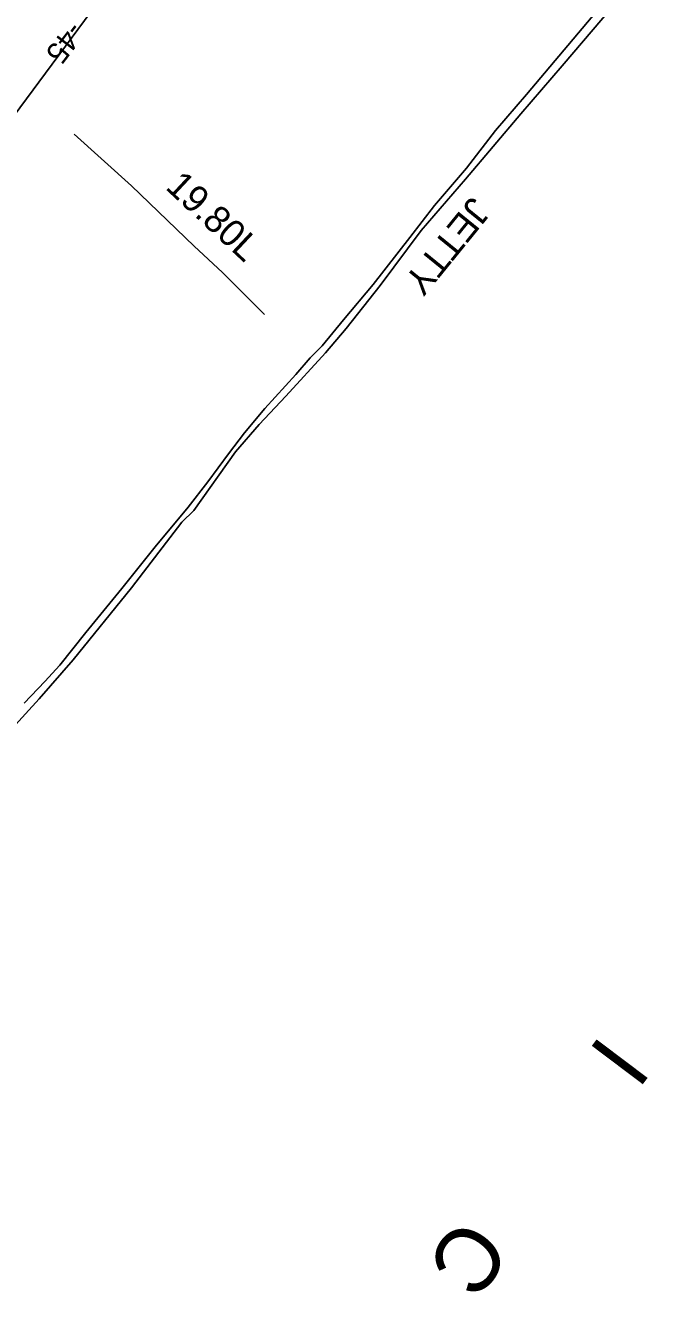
# Model space of a CAD drawing. Extents: x 3879599 to 3900814, y 146526 to 168888.
# Drawn here: x 3891224 to 3892197, y 152191 to 154174 of the extents above; entities that cross this region are included whole.
import ezdxf

# ---------------------------------------------------------------- set-up
doc = ezdxf.new("R2010")
doc.units = 0
for name, color, linetype in [('V-LEVE-TOET', 7, 'Continuous'), ('V-RIVR-IDEN', 7, 'Continuous'), ('V-RIVR-JETY', 7, 'Continuous'), ('V-RIVR-RANG', 7, 'Continuous'), ('V-STRM-FMON', 7, 'Continuous'), ('V-TOPO-DPTH', 7, 'Continuous')]:
    doc.layers.add(name, color=color, linetype=linetype)

msp = doc.modelspace()

# ---------------------------------------------------------------- linework, layer by layer
at = {"layer": 'V-LEVE-TOET'}
msp.add_lwpolyline([(3891598, 153721.7), (3891532.2, 153787.4), (3891488, 153828.6), (3891389.7, 153922.8), (3891300.1, 154003.5)], dxfattribs=at)
at = {"layer": 'V-RIVR-JETY'}
for points in [[(3891478.4, 153419.9), (3891509.4, 153459.7), (3891541.4, 153503.7), (3891566.8, 153536.3), (3891598.5, 153574.2), (3891647.1, 153627.9), (3891669.2, 153653.6), (3891688.3, 153672.4), (3891721.5, 153713), (3891768.2, 153768.5), (3891825.3, 153842), (3891863.7, 153892.2), (3891913.8, 153950.4), (3891959.3, 154009.7), (3892007.9, 154065.7), (3892081.1, 154152.3), (3892145.8, 154229.3)], [(3892142.7, 154203.1), (3892063.5, 154110.7), (3891999.2, 154035.6), (3891912.5, 153933.3), (3891843, 153852.9), (3891779.2, 153766.8), (3891725.5, 153699.4), (3891693.4, 153661.8), (3891631.6, 153594), (3891589.7, 153549.5), (3891552.7, 153506.5), (3891487.2, 153415.1), (3891468.8, 153396.7)], [(3891222.1, 153113.5), (3891254.3, 153147.2), (3891277.9, 153172.9), (3891318.6, 153224.2), (3891375, 153292.8), (3891429.1, 153360.6), (3891463.4, 153401.9), (3891478.4, 153419.9)], [(3891468.8, 153396.7), (3891390.1, 153293.7), (3891298.6, 153181.1), (3891245.6, 153120.2), (3891197.3, 153067.3), (3891166.7, 153029.4), (3891146.1, 153004.8), (3891120.7, 152977.2), (3891084.9, 152927.5), (3891035.4, 152854.5), (3890985.4, 152790.9), (3890941, 152738), (3890883.7, 152678.2), (3890811.7, 152615.5), (3890745, 152553.6), (3890711.6, 152527.1), (3890646.5, 152483.4), (3890615.7, 152466.3), (3890539.2, 152428.2), (3890514.7, 152415)]]:
    msp.add_lwpolyline(points, dxfattribs=at)
at = {"layer": 'V-TOPO-DPTH'}
msp.add_lwpolyline([(3891753.9, 154772.9), (3891153.5, 153962.5)], dxfattribs=at)

# ---------------------------------------------------------------- texts
at = {"layer": 'V-RIVR-IDEN'}
for s, p in [('I', (3892125, 152597.1)), ('C', (3891906.7, 152313.3))]:
    msp.add_text(s, height=100, rotation=232.9925, dxfattribs=at).set_placement(p)
at = {"layer": 'V-RIVR-JETY'}
msp.add_text('JETTY', height=42, rotation=230.9182, dxfattribs=at).set_placement((3891922.2, 153907.9))
at = {"layer": 'V-RIVR-RANG'}
msp.add_text('-45', height=33.5, rotation=232.6215, dxfattribs=at).set_placement((3891293.2, 154182.3))
at = {"layer": 'V-STRM-FMON'}
msp.add_text('19.80L', height=42, rotation=316.914, dxfattribs=at).set_placement((3891441.4, 153919.1))

doc.saveas('drawing.dxf')
